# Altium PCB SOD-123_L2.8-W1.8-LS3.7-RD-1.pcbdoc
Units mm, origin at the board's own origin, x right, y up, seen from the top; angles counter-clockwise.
Board outline 17.03 x 14.6 mm, 2 copper layers (Top Layer, Bottom Layer), stack 0 mm thick; 1 components, 0 nets, 2 pads, 0 vias.
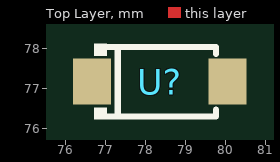
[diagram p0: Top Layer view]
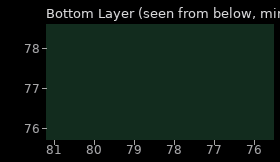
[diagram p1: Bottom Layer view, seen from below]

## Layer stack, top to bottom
Top Layer: signal copper (thickness not stored)
Bottom Layer: signal copper (thickness not stored)

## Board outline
86.885,69.85 69.85,69.85 69.85,84.452 86.885,84.452

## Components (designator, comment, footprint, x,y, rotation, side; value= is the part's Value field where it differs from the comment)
U? "" SOD-123_L2.8-W1.8-LS3.7-RD-1 78.367,77.16 r0 top

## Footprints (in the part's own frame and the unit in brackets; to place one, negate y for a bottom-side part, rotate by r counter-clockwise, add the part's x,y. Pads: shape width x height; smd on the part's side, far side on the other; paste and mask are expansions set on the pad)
SOD-123_L2.8-W1.8-LS3.7-RD-1 [mm]
  rect 0.95x1.15 smd: 1(-1.692,0) 2(1.692,0)
  silkscreen extent -1.63,-0.94 1.41,0.94

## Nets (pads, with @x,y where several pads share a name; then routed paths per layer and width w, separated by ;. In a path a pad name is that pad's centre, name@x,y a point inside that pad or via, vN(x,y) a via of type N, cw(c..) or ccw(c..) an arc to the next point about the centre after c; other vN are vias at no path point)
pads on no net: U?.1 U?.2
